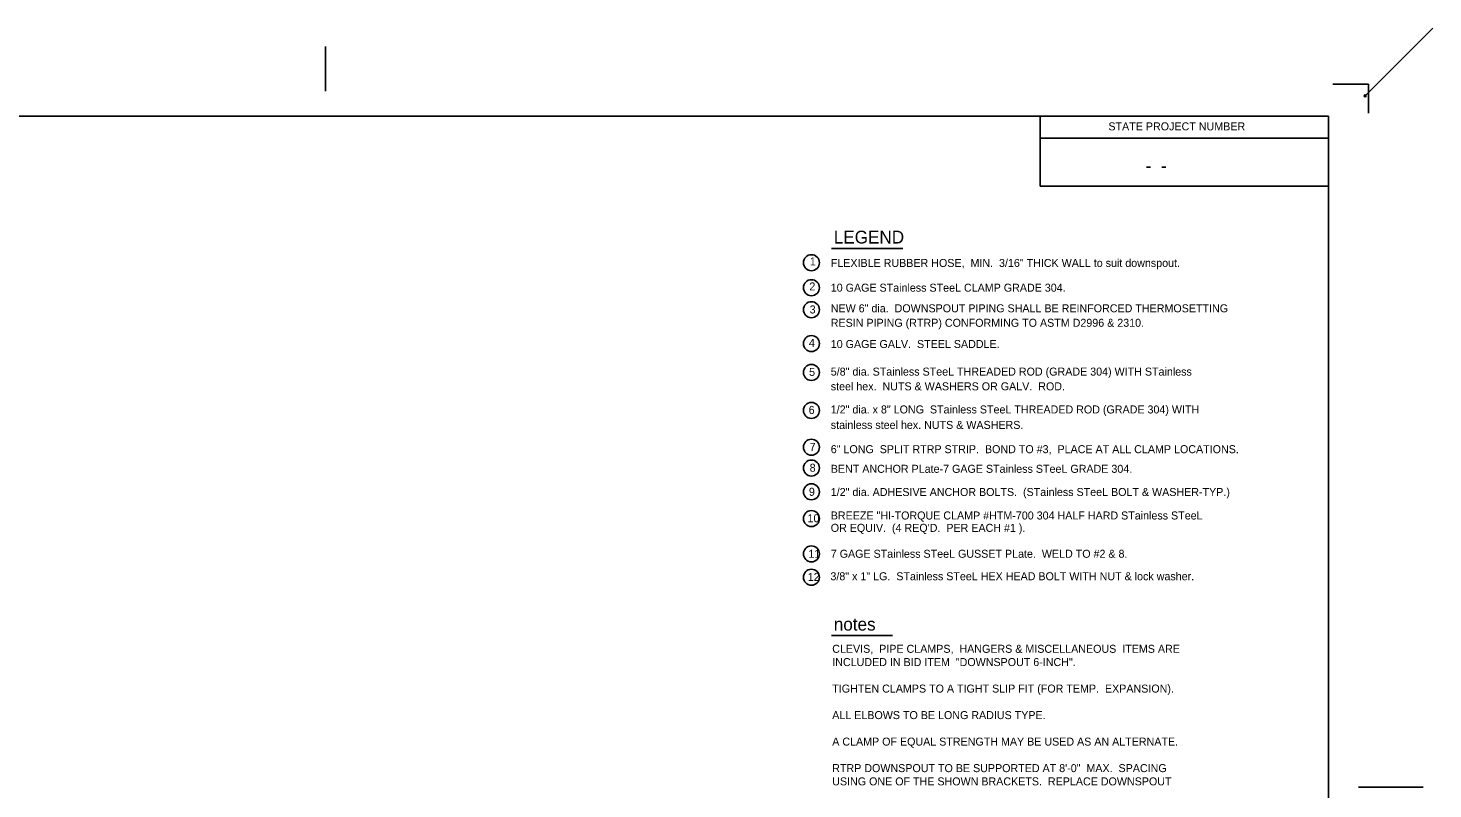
# Model space of a CAD drawing. Extents: x 15000 to 15012.1, y 999.8 to 1007.9.
# Drawn here: x 15004.73 to 15012.05, y 1003.78 to 1007.74 of the extents above; entities that cross this region are included whole.
import ezdxf

# ---------------------------------------------------------------- set-up
doc = ezdxf.new("R2010")
doc.units = 0
for name, color, linetype in [('b_title text', 7, 'Continuous'), ('Level 1', 7, 'Continuous'), ('Level 2', 7, 'Continuous'), ('Level 37', 7, 'Continuous'), ('Level 49', 7, 'Continuous')]:
    doc.layers.add(name, color=color, linetype=linetype)

msp = doc.modelspace()

# ---------------------------------------------------------------- linework, layer by layer
at = {"layer": 'b_title text'}
for p, q in [((15008.9179, 1006.5914), (15009.2894, 1006.5914)), ((15008.9179, 1004.5751), (15009.2351, 1004.5751))]:
    msp.add_line(p, q, dxfattribs=at)
at = {"layer": 'Level 1'}
for p, q in [((15011.714, 1007.4479), (15011.5294, 1007.4479)), ((15011.714, 1007.2964), (15011.714, 1007.4479)), ((15011.5058, 1007.2814), (15001.0578, 1007.2814)), ((15010.0053, 1007.2814), (15010.0053, 1006.9166)), ((15011.5058, 1000.2885), (15011.5058, 1007.2814)), ((15010.0053, 1007.1667), (15011.5058, 1007.1667)), ((15010.0053, 1006.9166), (15011.5058, 1006.9166))]:
    msp.add_line(p, q, dxfattribs=at)
at = {"layer": 'Level 2'}
msp.add_line((15011.697, 1007.3865), (15012.0502, 1007.7397), dxfattribs=at)
for centre in [(15008.8132, 1006.5177), (15008.8132, 1006.3875), (15008.8132, 1006.2729), (15008.8132, 1006.0963), (15008.8132, 1005.9458), (15008.8132, 1005.748), (15008.8132, 1005.5565), (15008.8132, 1005.4481), (15008.8132, 1005.3241), (15008.8132, 1005.1846), (15008.8132, 1005.001), (15008.8132, 1004.8789)]:
    msp.add_circle(centre, 0.0417, dxfattribs=at)
at = {"layer": 'Level 37'}
for p, q in [((15006.2818, 1007.4105), (15006.2818, 1007.6437)), ((15011.6624, 1003.7849), (15011.9988, 1003.7849))]:
    msp.add_line(p, q, dxfattribs=at)
at = {"layer": 'Level 49'}
msp.add_circle((15011.6969, 1007.3865), 0.00506, dxfattribs=at)

# ---------------------------------------------------------------- texts
at = {"layer": 'b_title text'}
for s, p in [('LEGEND', (15008.9299, 1006.6176)), ('notes', (15008.9299, 1004.6013))]:
    msp.add_text(s, height=0.0666, dxfattribs=at).set_placement(p)
at = {"layer": 'Level 1'}
for s, height, p in [('STATE PROJECT NUMBER', 0.041708, (15010.36, 1007.2069)), ('    -  -  ', 0.06735, (15010.4538, 1006.9895))]:
    msp.add_text(s, height=height, dxfattribs=at).set_placement(p)
at = {"layer": 'Level 2'}
for s, height, p in [('1', 0.0417, (15008.805, 1006.5031)), ('FLEXIBLE RUBBER HOSE,  MIN.  3/16" THICK WALL to suit downspout.', 0.041667, (15008.9141, 1006.4954)), ('2', 0.0417, (15008.8025, 1006.3729)), ('10 GAGE STainless STeeL CLAMP GRADE 304.', 0.041667, (15008.9141, 1006.3666)), ('3', 0.0417, (15008.8042, 1006.2532)), ('NEW 6" dia.  DOWNSPOUT PIPING SHALL BE REINFORCED THERMOSETTING', 0.041667, (15008.9141, 1006.2592)), ('RESIN PIPING (RTRP) CONFORMING TO ASTM D2996 & 2310.', 0.041667, (15008.9141, 1006.1838)), ('4', 0.0417, (15008.8003, 1006.0793)), ('10 GAGE GALV.  STEEL SADDLE.', 0.041667, (15008.9141, 1006.0731)), ('5', 0.0417, (15008.8013, 1005.9277)), ('5/8" dia. STainless STeeL THREADED ROD (GRADE 304) WITH STainless', 0.041667, (15008.9141, 1005.9295)), ('steel hex.  NUTS & WASHERS OR GALV.  ROD.', 0.041667, (15008.9141, 1005.8527)), ('6', 0.0417, (15008.799, 1005.7298)), ('1/2" dia. x 8" LONG  STainless STeeL THREADED ROD (GRADE 304) WITH', 0.041667, (15008.9141, 1005.7323)), ('stainless steel hex. NUTS & WASHERS. ', 0.041667, (15008.9141, 1005.6518)), ('7', 0.0417, (15008.804, 1005.5372)), ('6" LONG  SPLIT RTRP STRIP.  BOND TO #3,  PLACE AT ALL CLAMP LOCATIONS.', 0.041667, (15008.9141, 1005.5254)), ('8', 0.0417, (15008.8043, 1005.4288)), ('BENT ANCHOR PLate-7 GAGE STainless STeeL GRADE 304.', 0.041667, (15008.9141, 1005.4231)), ('9', 0.0417, (15008.8003, 1005.3034)), ('1/2" dia. ADHESIVE ANCHOR BOLTS.  (STainless STeeL BOLT & WASHER-TYP.)', 0.041667, (15008.9141, 1005.3023)), ('BREEZE "HI-TORQUE CLAMP #HTM-700 304 HALF HARD STainless STeeL', 0.041667, (15008.9141, 1005.18)), ('10', 0.04167, (15008.7931, 1005.1657)), ("OR EQUIV.  (4 REQ'D.  PER EACH #1 ).", 0.041667, (15008.9141, 1005.1156)), ('11', 0.04167, (15008.7978, 1004.9807)), ('7 GAGE STainless STeeL GUSSET PLate.  WELD TO #2 & 8.', 0.041667, (15008.9141, 1004.9806)), ('12', 0.04167, (15008.7944, 1004.86)), ('3/8" x 1" LG.  STainless STeeL HEX HEAD BOLT WITH NUT & lock washer.', 0.041667, (15008.9124, 1004.8634)), ('CLEVIS,  PIPE CLAMPS,  HANGERS & MISCELLANEOUS  ITEMS ARE ', 0.041651, (15008.9218, 1004.4855)), ('INCLUDED IN BID ITEM  "DOWNSPOUT 6-INCH".', 0.041651, (15008.9218, 1004.4164)), ('TIGHTEN CLAMPS TO A TIGHT SLIP FIT (FOR TEMP.  EXPANSION).', 0.041651, (15008.9218, 1004.2783)), ('ALL ELBOWS TO BE LONG RADIUS TYPE.', 0.041651, (15008.9218, 1004.1402)), ('A CLAMP OF EQUAL STRENGTH MAY BE USED AS AN ALTERNATE.', 0.041651, (15008.9218, 1004.0021)), ('RTRP DOWNSPOUT TO BE SUPPORTED AT 8\'-0"  MAX.  SPACING ', 0.041651, (15008.9218, 1003.864)), ('USING ONE OF THE SHOWN BRACKETS.  REPLACE DOWNSPOUT ', 0.041651, (15008.9218, 1003.7949))]:
    msp.add_text(s, height=height, dxfattribs=at).set_placement(p)

doc.saveas('drawing.dxf')
